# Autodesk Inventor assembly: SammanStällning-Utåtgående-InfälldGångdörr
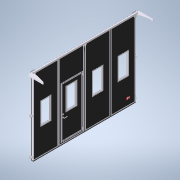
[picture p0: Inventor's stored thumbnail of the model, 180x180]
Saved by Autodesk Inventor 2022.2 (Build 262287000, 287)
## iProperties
Created: 2022-02
Part Number: SammanStällning-Utåtgående-InfälldGångdörr
Document SubType Name: Assembly
Designer: cl
Author: cl
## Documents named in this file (20)
- G:\AutoCad\Carl Lund\3D-modeller systemlösningar\3D-modell-systemlösning-2022\SammanStällning-Utåtgående-InfälldGångdörr.iam
- G:\AutoCad\Carl Lund\3D-modeller systemlösningar\3D-modell-systemlösning-2022\Parts\BladKomplett2022.iam
- G:\AutoCad\Carl Lund\3D-modeller systemlösningar\3D-modell-systemlösning-2022\Parts\MellanGångjärnH.ipt
- G:\AutoCad\Carl Lund\3D-modeller systemlösningar\3D-modell-systemlösning-2022\Parts\MellanGångjärnV.ipt
- G:\AutoCad\Carl Lund\3D-modeller systemlösningar\3D-modell-systemlösning-2022\Parts\Karmstyrning.ipt
- G:\AutoCad\Carl Lund\3D-modeller systemlösningar\3D-modell-systemlösning-2022\Parts\KarmgångjärnH.ipt
- G:\AutoCad\Carl Lund\3D-modeller systemlösningar\3D-modell-systemlösning-2022\Parts\KarmgångjärnV.ipt
- G:\AutoCad\Carl Lund\3D-modeller systemlösningar\3D-modell-systemlösning-2022\Parts\SidotätningUppe.ipt
- G:\AutoCad\Carl Lund\3D-modeller systemlösningar\3D-modell-systemlösning-2022\Parts\SidoTätning.ipt
- G:\AutoCad\Carl Lund\3D-modeller systemlösningar\3D-modell-systemlösning-2022\Parts\SläpList.ipt
- G:\AutoCad\Carl Lund\3D-modeller systemlösningar\3D-modell-systemlösning-2022\Parts\GummilistMellan.ipt
- G:\AutoCad\Carl Lund\3D-modeller systemlösningar\3D-modell-systemlösning-2022\Styrande.iam
- G:\AutoCad\Carl Lund\3D-modeller systemlösningar\3D-modell-systemlösning-2022\Parts\GarageregelHöger.ipt
- G:\AutoCad\Carl Lund\3D-modeller systemlösningar\3D-modell-systemlösning-2022\Parts\GarageregelVänster.ipt
- G:\AutoCad\Carl Lund\3D-modeller systemlösningar\3D-modell-systemlösning-2022\Parts\styrrulle.ipt
- G:\AutoCad\Carl Lund\3D-modeller systemlösningar\3D-modell-systemlösning-2022\Parts\Styrskena.ipt
- G:\AutoCad\Carl Lund\3D-modeller systemlösningar\3D-modell-systemlösning-2022\Parts\Uppställningsbeslag-H-Ut.ipt
- G:\AutoCad\Carl Lund\3D-modeller systemlösningar\3D-modell-systemlösning-2022\Parts\Uppställningsbeslag-V-Ut.ipt
- G:\AutoCad\Carl Lund\3D-modeller systemlösningar\3D-modell-systemlösning-2022\Parts\BladKomplettInfälld2022.iam
- G:\AutoCad\Carl Lund\3D-modeller systemlösningar\3D-modell-systemlösning-2022\Parts\Logga.ipt
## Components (50 placed, 18 different names)
1. Logga:1 — Mate:202, Mate:203, Mate:204
2. BladKomplett2022:1 [sub-assembly] — Mate:1, Mate:2, Flush:1, Flush:2, Flush:3, Flush:8, Flush:28, Flush:29, Mate:28, Flush:30, Mate:42, Mate:39, Flush:99, Flush:100, Flush:101, Flush:102, Flush:103, Flush:104, Mate:61, Mate:66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
3. BladKomplett2022:2 [sub-assembly] — Flush:2, Flush:3, Flush:8, Mate:65, Flush:148, Flush:149, Flush:171, Flush:177, Flush:178, Mate:182, Flush:181, Flush:184, Mate:196, Flush:215
4. BladKomplett2022:3 [sub-assembly] — Flush:30, Flush:101, Flush:102, Mate:183, Flush:185, Flush:186, Flush:189, Flush:192
5. BladKomplett2022:4 [sub-assembly] — Flush:32, Flush:100, Flush:103, Mate:64, Flush:146, Flush:147, Mate:184, Flush:193, Flush:194, Flush:197
6. BladKomplett2022:5 [sub-assembly] — Flush:31, Flush:99, Flush:104, Mate:63, Flush:144, Flush:145, Mate:81, Flush:168, Flush:200, Mate:185, Flush:201, Flush:202, Flush:205, Flush:208, Flush:219
7. BladKomplettInfälld2022:1 [sub-assembly] — Flush:220, Flush:221, Flush:222, Mate:198, Flush:223, Flush:224, Flush:227, Flush:230, Flush:231, Flush:232, Mate:200, Flush:233, Mate:201, Flush:234
8. BladKomplett2022:6 [sub-assembly] — Mate:28, Flush:28, Flush:29, Flush:31, Flush:32, Mate:38, Flush:138, Flush:139, Mate:58, Mate:62, Flush:142, Flush:143, Mate:69, Mate:78, Flush:159, Flush:160, Mate:180, Mate:186, Mate:187, Mate:192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
9. GarageregelHöger:1 — Flush:156, Flush:157, Flush:158
10. GarageregelHöger:2 — Mate:77, Flush:154, Flush:155, Flush:156, Flush:157, Flush:158
11. GarageregelVänster:1 — Flush:161, Flush:162, Flush:163
12. GarageregelVänster:2 — Mate:78, Flush:159, Flush:160, Flush:161, Flush:162, Flush:163
13. Karmstyrning:2 — Mate:38, Flush:138, Mate:186, Flush:209
14. Karmstyrning:3 — Mate:39, Mate:189, Flush:210
15. Karmstyrning:4 — Mate:42, Mate:61, Mate:188, Flush:209
16. KarmgångjärnH:1 — Mate:190, Mate:191, Flush:211, Flush:213, Flush:214
17. KarmgångjärnV:1 — Mate:192, Flush:212, Mate:193, Flush:217, Flush:218
18. Karmstyrning:1 — Flush:139, Mate:58, Mate:187, Flush:210
19. MellanGångjärnH:7 — Flush:177, Flush:178, Mate:182, Flush:179, Flush:180
20. MellanGångjärnH:8 — Flush:179, Flush:180, Flush:181, Flush:182, Flush:183
21. MellanGångjärnH:9 — Flush:182, Flush:183, Flush:184
22. MellanGångjärnV:7 — Mate:183, Flush:185, Flush:186, Flush:187, Flush:188
23. MellanGångjärnV:8 — Flush:187, Flush:188, Flush:189, Flush:190, Flush:191
24. MellanGångjärnV:9 — Flush:190, Flush:191, Flush:192
25. MellanGångjärnH:10 — Flush:198, Flush:199, Flush:200
26. MellanGångjärnH:11 — Flush:195, Flush:196, Flush:197, Flush:198, Flush:199
27. MellanGångjärnH:12 — Mate:184, Flush:193, Flush:194, Flush:195, Flush:196
28. MellanGångjärnV:10 — Mate:185, Flush:201, Flush:202, Flush:203, Flush:204
29. MellanGångjärnV:11 — Flush:203, Flush:204, Flush:205, Flush:206, Flush:207
30. MellanGångjärnV:12 — Flush:206, Flush:207, Flush:208
31. MellanGångjärnH:13 — Flush:225, Flush:226, Flush:227, Flush:228, Flush:229
32. MellanGångjärnH:14 — Flush:228, Flush:229, Flush:230
33. MellanGångjärnH:15 — Mate:198, Flush:223, Flush:224, Flush:225, Flush:226
34. GummilistMellan:6 — Flush:233, Mate:201, Flush:234
35. GummilistMellan:2 — Mate:63, Flush:144, Flush:145
36. GummilistMellan:3 — Mate:64, Flush:146, Flush:147
37. GummilistMellan:4 — Mate:65, Flush:148, Flush:149
38. GummilistMellan:5 — Mate:66, Flush:150, Flush:151
39. SidotätningUppe:1 — Mate:68, Mate:178, Flush:176, Mate:179, Mate:181
40. SidoTätning:1 — Mate:69, Mate:76, Mate:180, Mate:181
41. SidoTätning:2 — Mate:72, Mate:177, Mate:179
42. SläpList:1 — Mate:75, Flush:153, Mate:76
43. GummilistMellan:1 — Mate:62, Flush:142, Flush:143
44. styrrulle:3 — Flush:231, Flush:232, Mate:200
45. Uppställningsbeslag-H-Ut:1 — Flush:213, Flush:214, Mate:194, Mate:195, Flush:216, Mate:199
46. Uppställningsbeslag-V-Ut:1 — Flush:217, Mate:197, Flush:218
47. styrrulle:1 — Mate:81, Flush:168, Flush:219
48. styrrulle:2 — Flush:171, Mate:196, Flush:215
49. Styrskena:1 — Flush:174, Mate:176, Flush:175, Mate:195, Flush:216, Mate:199
50. Styrskena:2 — Flush:174, Mate:176, Flush:175
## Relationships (151: Flush 101, Mate 50)
- Mate:1: BladKomplett2022:1
- Mate:2: BladKomplett2022:1
- Flush:1: BladKomplett2022:1
- Flush:2: BladKomplett2022:1 ↔ BladKomplett2022:2
- Flush:3: BladKomplett2022:1 ↔ BladKomplett2022:2
- Flush:8: BladKomplett2022:1 ↔ BladKomplett2022:2
- Mate:28: BladKomplett2022:1 ↔ BladKomplett2022:6
- Flush:28: BladKomplett2022:1 ↔ BladKomplett2022:6
- Flush:29: BladKomplett2022:1 ↔ BladKomplett2022:6
- Flush:30: BladKomplett2022:1 ↔ BladKomplett2022:3
- Flush:31: BladKomplett2022:5 ↔ BladKomplett2022:6
- Flush:32: BladKomplett2022:4 ↔ BladKomplett2022:6
- Mate:38: BladKomplett2022:6 ↔ Karmstyrning:2
- Mate:39: BladKomplett2022:1 ↔ Karmstyrning:3
- Mate:42: BladKomplett2022:1 ↔ Karmstyrning:4
- Flush:99: BladKomplett2022:1 ↔ BladKomplett2022:5
- Flush:100: BladKomplett2022:1 ↔ BladKomplett2022:4
- Flush:101: BladKomplett2022:1 ↔ BladKomplett2022:3
- Flush:102: BladKomplett2022:1 ↔ BladKomplett2022:3
- Flush:103: BladKomplett2022:1 ↔ BladKomplett2022:4
- Flush:104: BladKomplett2022:1 ↔ BladKomplett2022:5
- Flush:138: BladKomplett2022:6 ↔ Karmstyrning:2
- Flush:139: BladKomplett2022:6 ↔ Karmstyrning:1
- Mate:58: BladKomplett2022:6 ↔ Karmstyrning:1
- Mate:61: BladKomplett2022:1 ↔ Karmstyrning:4
- Mate:62: BladKomplett2022:6 ↔ GummilistMellan:1
- Flush:142: BladKomplett2022:6 ↔ GummilistMellan:1
- Flush:143: BladKomplett2022:6 ↔ GummilistMellan:1
- Mate:63: BladKomplett2022:5 ↔ GummilistMellan:2
- Flush:144: BladKomplett2022:5 ↔ GummilistMellan:2
- Flush:145: BladKomplett2022:5 ↔ GummilistMellan:2
- Mate:64: BladKomplett2022:4 ↔ GummilistMellan:3
- Flush:146: BladKomplett2022:4 ↔ GummilistMellan:3
- Flush:147: BladKomplett2022:4 ↔ GummilistMellan:3
- Mate:65: BladKomplett2022:2 ↔ GummilistMellan:4
- Flush:148: BladKomplett2022:2 ↔ GummilistMellan:4
- Flush:149: BladKomplett2022:2 ↔ GummilistMellan:4
- Mate:66: BladKomplett2022:1 ↔ GummilistMellan:5
- Flush:150: BladKomplett2022:1 ↔ GummilistMellan:5
- Flush:151: BladKomplett2022:1 ↔ GummilistMellan:5
- Mate:68: BladKomplett2022:1 ↔ SidotätningUppe:1
- Mate:69: BladKomplett2022:6 ↔ SidoTätning:1
- Mate:72: BladKomplett2022:1 ↔ SidoTätning:2
- Mate:75: BladKomplett2022:1 ↔ SläpList:1
- Flush:153: BladKomplett2022:1 ↔ SläpList:1
- Mate:76: SidoTätning:1 ↔ SläpList:1
- Mate:77: BladKomplett2022:1 ↔ GarageregelHöger:2
- Flush:154: BladKomplett2022:1 ↔ GarageregelHöger:2
- Flush:155: BladKomplett2022:1 ↔ GarageregelHöger:2
- Flush:156: GarageregelHöger:1 ↔ GarageregelHöger:2
- Flush:157: GarageregelHöger:1 ↔ GarageregelHöger:2
- Flush:158: GarageregelHöger:1 ↔ GarageregelHöger:2
- Mate:78: BladKomplett2022:6 ↔ GarageregelVänster:2
- Flush:159: BladKomplett2022:6 ↔ GarageregelVänster:2
- Flush:160: BladKomplett2022:6 ↔ GarageregelVänster:2
- Flush:161: GarageregelVänster:1 ↔ GarageregelVänster:2
- Flush:162: GarageregelVänster:1 ↔ GarageregelVänster:2
- Flush:163: GarageregelVänster:1 ↔ GarageregelVänster:2
- Mate:81: BladKomplett2022:5 ↔ styrrulle:1
- Flush:168: BladKomplett2022:5 ↔ styrrulle:1
- Flush:171: BladKomplett2022:2 ↔ styrrulle:2
- Flush:174: Styrskena:1 ↔ Styrskena:2
- Mate:176: Styrskena:1 ↔ Styrskena:2
- Flush:175: Styrskena:1 ↔ Styrskena:2
- Mate:177: BladKomplett2022:1 ↔ SidoTätning:2
- Mate:178: BladKomplett2022:1 ↔ SidotätningUppe:1
- Flush:176: BladKomplett2022:1 ↔ SidotätningUppe:1
- Mate:179: SidotätningUppe:1 ↔ SidoTätning:2
- Mate:180: BladKomplett2022:6 ↔ SidoTätning:1
- Mate:181: SidotätningUppe:1 ↔ SidoTätning:1
- Flush:177: BladKomplett2022:2 ↔ MellanGångjärnH:7
- Flush:178: BladKomplett2022:2 ↔ MellanGångjärnH:7
- Mate:182: BladKomplett2022:2 ↔ MellanGångjärnH:7
- Flush:179: MellanGångjärnH:7 ↔ MellanGångjärnH:8
- Flush:180: MellanGångjärnH:7 ↔ MellanGångjärnH:8
- Flush:181: BladKomplett2022:2 ↔ MellanGångjärnH:8
- Flush:182: MellanGångjärnH:8 ↔ MellanGångjärnH:9
- Flush:183: MellanGångjärnH:8 ↔ MellanGångjärnH:9
- Flush:184: BladKomplett2022:2 ↔ MellanGångjärnH:9
- Mate:183: BladKomplett2022:3 ↔ MellanGångjärnV:7
- Flush:185: BladKomplett2022:3 ↔ MellanGångjärnV:7
- Flush:186: BladKomplett2022:3 ↔ MellanGångjärnV:7
- Flush:187: MellanGångjärnV:7 ↔ MellanGångjärnV:8
- Flush:188: MellanGångjärnV:7 ↔ MellanGångjärnV:8
- Flush:189: BladKomplett2022:3 ↔ MellanGångjärnV:8
- Flush:190: MellanGångjärnV:8 ↔ MellanGångjärnV:9
- Flush:191: MellanGångjärnV:8 ↔ MellanGångjärnV:9
- Flush:192: BladKomplett2022:3 ↔ MellanGångjärnV:9
- Mate:184: BladKomplett2022:4 ↔ MellanGångjärnH:12
- Flush:193: BladKomplett2022:4 ↔ MellanGångjärnH:12
- Flush:194: BladKomplett2022:4 ↔ MellanGångjärnH:12
- Flush:195: MellanGångjärnH:11 ↔ MellanGångjärnH:12
- Flush:196: MellanGångjärnH:11 ↔ MellanGångjärnH:12
- Flush:197: BladKomplett2022:4 ↔ MellanGångjärnH:11
- Flush:198: MellanGångjärnH:10 ↔ MellanGångjärnH:11
- Flush:199: MellanGångjärnH:10 ↔ MellanGångjärnH:11
- Flush:200: BladKomplett2022:5 ↔ MellanGångjärnH:10
- Mate:185: BladKomplett2022:5 ↔ MellanGångjärnV:10
- Flush:201: BladKomplett2022:5 ↔ MellanGångjärnV:10
- Flush:202: BladKomplett2022:5 ↔ MellanGångjärnV:10
- Flush:203: MellanGångjärnV:10 ↔ MellanGångjärnV:11
- Flush:204: MellanGångjärnV:10 ↔ MellanGångjärnV:11
- Flush:205: BladKomplett2022:5 ↔ MellanGångjärnV:11
- Flush:206: MellanGångjärnV:11 ↔ MellanGångjärnV:12
- Flush:207: MellanGångjärnV:11 ↔ MellanGångjärnV:12
- Flush:208: BladKomplett2022:5 ↔ MellanGångjärnV:12
- Mate:186: BladKomplett2022:6 ↔ Karmstyrning:2
- Mate:187: BladKomplett2022:6 ↔ Karmstyrning:1
- Mate:188: BladKomplett2022:1 ↔ Karmstyrning:4
- Flush:209: Karmstyrning:2 ↔ Karmstyrning:4
- Mate:189: BladKomplett2022:1 ↔ Karmstyrning:3
- Flush:210: Karmstyrning:3 ↔ Karmstyrning:1
- Mate:190: BladKomplett2022:1 ↔ KarmgångjärnH:1
- Mate:191: BladKomplett2022:1 ↔ KarmgångjärnH:1
- Flush:211: BladKomplett2022:1 ↔ KarmgångjärnH:1
- Mate:192: BladKomplett2022:6 ↔ KarmgångjärnV:1
- Flush:212: BladKomplett2022:6 ↔ KarmgångjärnV:1
- Mate:193: BladKomplett2022:6 ↔ KarmgångjärnV:1
- Flush:213: KarmgångjärnH:1 ↔ Uppställningsbeslag-H-Ut:1
- Flush:214: KarmgångjärnH:1 ↔ Uppställningsbeslag-H-Ut:1
- Mate:194: BladKomplett2022:1 ↔ Uppställningsbeslag-H-Ut:1
- Mate:195: Uppställningsbeslag-H-Ut:1 ↔ Styrskena:1
- Mate:196: BladKomplett2022:2 ↔ styrrulle:2
- Flush:215: BladKomplett2022:2 ↔ styrrulle:2
- Flush:216: Uppställningsbeslag-H-Ut:1 ↔ Styrskena:1
- Flush:217: KarmgångjärnV:1 ↔ Uppställningsbeslag-V-Ut:1
- Mate:197: BladKomplett2022:6 ↔ Uppställningsbeslag-V-Ut:1
- Flush:218: KarmgångjärnV:1 ↔ Uppställningsbeslag-V-Ut:1
- Flush:219: BladKomplett2022:5 ↔ styrrulle:1
- Flush:220: BladKomplett2022:1 ↔ BladKomplettInfälld2022:1
- Flush:221: BladKomplett2022:1 ↔ BladKomplettInfälld2022:1
- Flush:222: BladKomplett2022:1 ↔ BladKomplettInfälld2022:1
- Mate:198: BladKomplettInfälld2022:1 ↔ MellanGångjärnH:15
- Flush:223: BladKomplettInfälld2022:1 ↔ MellanGångjärnH:15
- Flush:224: BladKomplettInfälld2022:1 ↔ MellanGångjärnH:15
- Flush:225: MellanGångjärnH:13 ↔ MellanGångjärnH:15
- Flush:226: MellanGångjärnH:13 ↔ MellanGångjärnH:15
- Flush:227: BladKomplettInfälld2022:1 ↔ MellanGångjärnH:13
- Flush:228: MellanGångjärnH:13 ↔ MellanGångjärnH:14
- Flush:229: MellanGångjärnH:13 ↔ MellanGångjärnH:14
- Flush:230: BladKomplettInfälld2022:1 ↔ MellanGångjärnH:14
- Mate:199: Uppställningsbeslag-H-Ut:1 ↔ Styrskena:1
- Flush:231: BladKomplettInfälld2022:1 ↔ styrrulle:3
- Flush:232: BladKomplettInfälld2022:1 ↔ styrrulle:3
- Mate:200: BladKomplettInfälld2022:1 ↔ styrrulle:3
- Flush:233: BladKomplettInfälld2022:1 ↔ GummilistMellan:6
- Mate:201: BladKomplettInfälld2022:1 ↔ GummilistMellan:6
- Flush:234: BladKomplettInfälld2022:1 ↔ GummilistMellan:6
- Mate:202: Logga:1 ↔ BladKomplett2022:6
- Mate:203: Logga:1 ↔ BladKomplett2022:6
- Mate:204: Logga:1 ↔ BladKomplett2022:6
## Named parameters: Blad2 = 1012.5 mm, Blad3 = 0, Blad4 = 0, Blad5 = 1012.5 mm, MGJ12Djup = 0, MGJ12Bredd = 0, MGJ56Djup = 0, MGJ56Bredd = 0, MGJ23Djup = 48 mm, MGJ45Djup = 48 mm, GarageRegel5 = 0, GarageRegel6 = 0, BladBredd = 987.5 mm, Fönsterhöjd = 862 mm, Blad2_1 = 1012.5 mm, Blad3_1 = 0, Blad4_1 = 0, Blad5_1 = 1012.5 mm, Blad6 = 2025 mm, MGJ12Djup_1 = 0, MGJ12Bredd_1 = 0, MGJ2Djup = 0, MGJ2Bredd = 5012.5 mm, MGJ56Djup_1 = 0, MGJ56Bredd_1 = 0, MGJ23Djup_1 = 48 mm, MGJ45Djup_1 = 48 mm, GarageRegel5_1 = 0, GarageRegel6_1 = 0, Styrrulle2Djup = 0, FönsterhöjdStyrning = 862 mm, FönsterKarm = 54 mm, AndraGlasraden = 0, BrösthöjdStyrning2 = 0.0001 mm, InfälldGångDörr = 0, Infälldstyr = 1030.33333 mm
